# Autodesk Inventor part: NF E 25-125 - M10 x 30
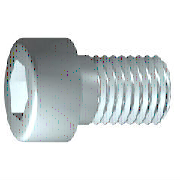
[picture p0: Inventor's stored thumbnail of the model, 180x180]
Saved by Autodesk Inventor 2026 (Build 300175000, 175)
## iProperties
IsCustomPart: 0
Created: 2025-01
Part Number: NF E 25-125 - M10 x 30
Material: Acier, doux
Description: Tête cylindrique fendue - Produit de classe A - Symbole C S
Document SubType Name: Modeling
Standard: NF E 25-125
Designer: thierry.jost
Standards Organization: AFNOR
Language: fr-FR
Size Designation: M10 x 30
Categories: <MemberInstance><Categories><Category DisplayName="Visserie" InternalName="e4da775c-781d-43d5-af7c-5136215cf5a6" Mnemonic="FSTN"><Category DisplayName="Vis" Int
Density: 7.85 g/cm^3
Appearance: Semi-poli
Author: thierry.jost
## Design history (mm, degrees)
body "Solid1"
workplane "Work Plane1"
fillet "Fillet2" dims "d30" = 0.1 (= R)
revolve "Corps" stored, may be unused: angle "d10" = 90 deg
sketch "Esquisse2"
  geometry: L1 (0, -11.2)-(0, 11.2) reference; L2 (-11.2, 0)-(11.2, 0) reference; L3 (4.619, 0)-(2.309, -4); L4 (2.309, -4)-(-2.309, -4); L5 (-2.309, -4)-(-4.619, 0); L6 (-4.619, 0)-(-2.309, 4); L7 (-2.309, 4)-(2.309, 4); L8 (2.309, 4)-(4.619, 0); 2 further points
  constraints: 12 end point, 1 coincident, 1 horizontal alignment, 1 point on line, 12 other
extrude "Rainure" join sketch "Esquisse2" stored distance "d11" = 10; taper "d12" = 0 deg
fillet "Congé1" dims "d17" = 1 (= RR)
feature "Filetage" dims "d13" = 26.25 (= GEL), "d14" = 0
chamfer "Chanfrein1" distance "d15" = 0.92018 (= -0.5 x SPD + 0.5 x GD); stored, may be unused: second distance "d16" = 0.92018 (= GUL), angle "d27" = 45 deg
sketch "Esquisse1"
  geometry: L1 (-2.333, 0)-(30, 0); L2 (30, 0)-(30, 5); L3 (30, 5)-(3.75, 5); L4 (3.75, 5)-(2.83, 5); L5 (2.83, 5)-(0, 5); L6 (0, 5)-(0, 8); L7 (0, 8)-(-10, 8); L8 (-10, 8)-(-10, 4.619); L9 (-10, 4.619)-(-5, 4.619); L10 (-5, 4.619)-(-2.333, 0); L11 (-18, 0)-(38, 0) reference; L12 (0, -1.6)-(0, 9.6) reference; L13 (3.75, 5)-(0, 5)
  constraints: 22 end point, 6 parallel, 2 collinear, 2 perpendicular, 1 horizontal, 1 point on line
  dimensions: "d1" = 26.25 distance from line of L3.end L2 (= GEL); "d2" = 0.92028 distance of L4.end L3.end (computed from GAL); "d3" = 10 distance between parallel lines of L8 L6 (= KOH); "d4" = 5 distance of L8.end L9.end (= INTI); "d5" = 60 deg angle of L10 L1; "d6" = 10 diameter of L3 L1 (= GD); "d7" = 10 diameter of L5 L1 (= BDM); "d8" = 9.2376 diameter of L9 L1 (= 1.1547 x SW); "d9" = 16 diameter of L7 L1 (= KOD); "d26" = 30 distance between parallel lines of L12 L2 (= NLG)
other parameters: "GD" = 10 (= NND) [user parameter; used in 2 equation terms], "NLG" = 30 [user parameter; used in 1 equation term], "GEL" = 26.25 [user parameter; used in 2 equation terms], "KOD" = 16 [user parameter; used in 1 equation term], "KOH" = 10 (= NND) [user parameter; used in 1 equation term], "INTI" = 5 [user parameter; used in 1 equation term], "GAL" = 0.92018 (= 0.61345 x PTC) [user parameter; used in 1 equation term], "GUL" = 0.92018 (= 0.61345 x PTC) [user parameter; used in 1 equation term], "BDM" = 10 (= NND) [user parameter; used in 1 equation term], "SW" = 8 [user parameter; used in 2 equation terms], "RR" = 1 [user parameter; used in 1 equation term], "SPD" = 8.15965 (= NND - 1.2269 x PTC) [user parameter; used in 1 equation term], "d19" = 0, "d28" = 0, "d29" = 0, "R" = 0.1 [user parameter; used in 1 equation term], "TOA" = 30 deg [user parameter], "GD1" = 8.15965 (= THREADDIA - 1.2269 x PTC) [user parameter], "FAWI" = 45 deg [user parameter], "TPU" = 6.66667 (computed from PTC) [user parameter], "PTC" = 1.5 [user parameter; used in 5 equation terms], "E0" = 9.24 (= 1.155 x SW) [user parameter]
